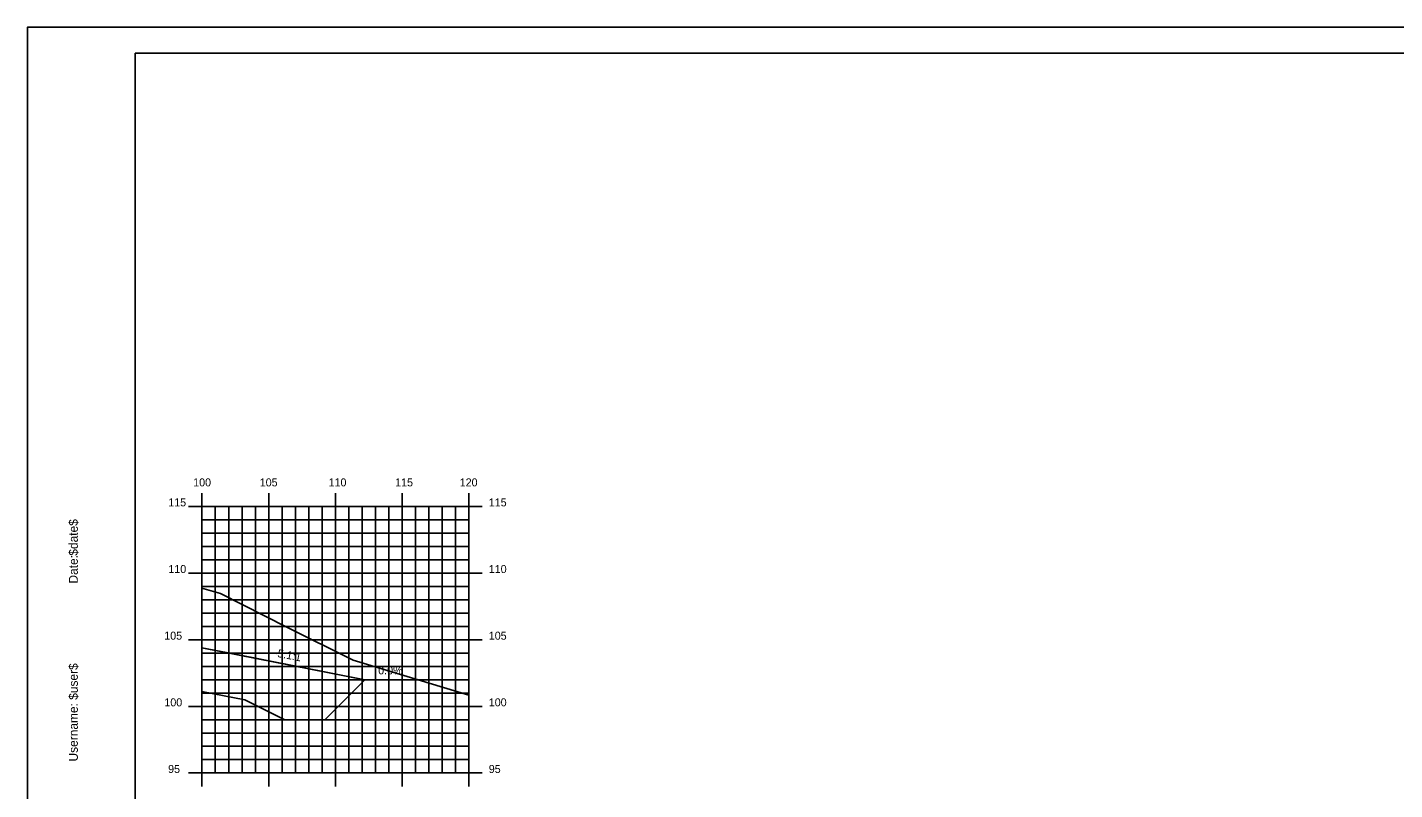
# Model space of a CAD drawing. Extents: x 850598 to 870284, y 366541 to 366651.
# Drawn here: x 856807 to 856909.5, y 366594 to 366651.2 of the extents above; entities that cross this region are included whole.
import ezdxf

# ---------------------------------------------------------------- set-up
doc = ezdxf.new("R2010")
doc.units = 0
for name, color, linetype in [('ANNOTATION', 7, 'Continuous'), ('BORDER', 7, 'Continuous'), ('D_Drainage_RipRap', 7, 'Continuous'), ('D_Roadway_Centerline', 7, 'Continuous'), ('D_Roadway_SlopeLines', 7, 'Continuous'), ('H_V ANNOTATION', 7, 'Continuous'), ('MAJOR', 7, 'Continuous'), ('MINOR', 7, 'Continuous'), ('PLOT BOUNDARY', 7, 'Continuous'), ('S_Roadway_Centerline', 7, 'Continuous')]:
    doc.layers.add(name, color=color, linetype=linetype)

msp = doc.modelspace()

# ---------------------------------------------------------------- linework, layer by layer
at = {"layer": 'BORDER'}
for p, q in [((856975.08, 366649.23), (856815.08, 366649.23)), ((856815.08, 366649.23), (856815.08, 366544.23))]:
    msp.add_line(p, q, dxfattribs=at)
at = {"layer": 'D_Drainage_RipRap'}
msp.add_lwpolyline([(856820.08, 366601.34), (856820.08, 366604.62), (856822.43, 366604.16), (856832.29, 366602.23), (856829.29, 366599.23), (856826.29, 366599.23), (856823.29, 366600.71)], close=True, dxfattribs=at)
at = {"layer": 'D_Roadway_Centerline'}
msp.add_lwpolyline([(856820.08, 366604.62), (856822.43, 366604.16), (856832.29, 366602.23), (856836.29, 366602.23)], dxfattribs=at)
at = {"layer": 'D_Roadway_SlopeLines'}
msp.add_lwpolyline([(856820.08, 366604.62), (856832.29, 366602.23)], dxfattribs=at)
at = {"layer": 'MAJOR'}
for p, q in [((856820.08, 366616.23), (856820.08, 366615.23)), ((856820.08, 366616.23), (856820.08, 366615.23)), ((856825.08, 366616.23), (856825.08, 366615.23)), ((856825.08, 366616.23), (856825.08, 366615.23)), ((856830.08, 366616.23), (856830.08, 366615.23)), ((856830.08, 366616.23), (856830.08, 366615.23)), ((856835.08, 366616.23), (856835.08, 366615.23)), ((856835.08, 366616.23), (856835.08, 366615.23)), ((856840.08, 366616.23), (856840.08, 366615.23)), ((856840.08, 366616.23), (856840.08, 366615.23)), ((856819.08, 366615.23), (856820.08, 366615.23)), ((856819.08, 366615.23), (856820.08, 366615.23)), ((856820.08, 366615.23), (856840.08, 366615.23)), ((856820.08, 366595.23), (856820.08, 366615.23)), ((856820.08, 366595.23), (856820.08, 366615.23)), ((856820.08, 366615.23), (856840.08, 366615.23)), ((856820.08, 366615.23), (856840.08, 366615.23)), ((856820.08, 366595.23), (856820.08, 366615.23)), ((856820.08, 366595.23), (856820.08, 366615.23)), ((856820.08, 366615.23), (856840.08, 366615.23)), ((856825.08, 366595.23), (856825.08, 366615.23)), ((856825.08, 366595.23), (856825.08, 366615.23)), ((856830.08, 366595.23), (856830.08, 366615.23)), ((856830.08, 366595.23), (856830.08, 366615.23)), ((856835.08, 366595.23), (856835.08, 366615.23)), ((856835.08, 366595.23), (856835.08, 366615.23)), ((856841.08, 366615.23), (856839.08, 366615.23)), ((856841.08, 366615.23), (856839.08, 366615.23)), ((856840.08, 366595.23), (856840.08, 366615.23)), ((856840.08, 366595.23), (856840.08, 366615.23)), ((856840.08, 366595.23), (856840.08, 366615.23)), ((856840.08, 366595.23), (856840.08, 366615.23)), ((856819.08, 366610.23), (856820.08, 366610.23)), ((856819.08, 366610.23), (856820.08, 366610.23)), ((856820.08, 366610.23), (856840.08, 366610.23)), ((856820.08, 366610.23), (856840.08, 366610.23)), ((856841.08, 366610.23), (856839.08, 366610.23)), ((856841.08, 366610.23), (856839.08, 366610.23)), ((856819.08, 366605.23), (856820.08, 366605.23)), ((856819.08, 366605.23), (856820.08, 366605.23)), ((856820.08, 366605.23), (856840.08, 366605.23)), ((856820.08, 366605.23), (856840.08, 366605.23)), ((856841.08, 366605.23), (856839.08, 366605.23)), ((856841.08, 366605.23), (856839.08, 366605.23)), ((856819.08, 366600.23), (856820.08, 366600.23)), ((856819.08, 366600.23), (856820.08, 366600.23)), ((856820.08, 366600.23), (856840.08, 366600.23)), ((856820.08, 366600.23), (856840.08, 366600.23)), ((856841.08, 366600.23), (856839.08, 366600.23)), ((856841.08, 366600.23), (856839.08, 366600.23)), ((856819.08, 366595.23), (856820.08, 366595.23)), ((856819.08, 366595.23), (856820.08, 366595.23)), ((856820.08, 366595.23), (856840.08, 366595.23)), ((856820.08, 366595.23), (856840.08, 366595.23)), ((856820.08, 366594.22), (856820.08, 366595.23)), ((856820.08, 366595.23), (856840.08, 366595.23)), ((856820.08, 366595.23), (856840.08, 366595.23)), ((856820.08, 366594.22), (856820.08, 366595.23)), ((856825.08, 366594.22), (856825.08, 366595.23)), ((856825.08, 366594.22), (856825.08, 366595.23)), ((856830.08, 366594.22), (856830.08, 366595.23)), ((856830.08, 366594.22), (856830.08, 366595.23)), ((856835.08, 366594.22), (856835.08, 366595.23)), ((856835.08, 366594.22), (856835.08, 366595.23)), ((856841.08, 366595.23), (856839.08, 366595.23)), ((856841.08, 366595.23), (856839.08, 366595.23)), ((856840.08, 366594.22), (856840.08, 366595.23)), ((856840.08, 366594.22), (856840.08, 366595.23))]:
    msp.add_line(p, q, dxfattribs=at)
at = {"layer": 'MINOR'}
for p, q in [((856821.08, 366595.23), (856821.08, 366615.23)), ((856821.08, 366595.23), (856821.08, 366615.23)), ((856822.08, 366595.23), (856822.08, 366615.23)), ((856822.08, 366595.23), (856822.08, 366615.23)), ((856823.08, 366595.23), (856823.08, 366615.23)), ((856823.08, 366595.23), (856823.08, 366615.23)), ((856824.08, 366595.23), (856824.08, 366615.23)), ((856824.08, 366595.23), (856824.08, 366615.23)), ((856826.08, 366595.23), (856826.08, 366615.23)), ((856826.08, 366595.23), (856826.08, 366615.23)), ((856827.08, 366595.23), (856827.08, 366615.23)), ((856827.08, 366595.23), (856827.08, 366615.23)), ((856828.08, 366595.23), (856828.08, 366615.23)), ((856828.08, 366595.23), (856828.08, 366615.23)), ((856829.08, 366595.23), (856829.08, 366615.23)), ((856829.08, 366595.23), (856829.08, 366615.23)), ((856831.08, 366595.23), (856831.08, 366615.23)), ((856831.08, 366595.23), (856831.08, 366615.23)), ((856832.08, 366595.23), (856832.08, 366615.23)), ((856832.08, 366595.23), (856832.08, 366615.23)), ((856833.08, 366595.23), (856833.08, 366615.23)), ((856833.08, 366595.23), (856833.08, 366615.23)), ((856834.08, 366595.23), (856834.08, 366615.23)), ((856834.08, 366595.23), (856834.08, 366615.23)), ((856836.08, 366595.23), (856836.08, 366615.23)), ((856836.08, 366595.23), (856836.08, 366615.23)), ((856837.08, 366595.23), (856837.08, 366615.23)), ((856837.08, 366595.23), (856837.08, 366615.23)), ((856838.08, 366595.23), (856838.08, 366615.23)), ((856838.08, 366595.23), (856838.08, 366615.23)), ((856839.08, 366595.23), (856839.08, 366615.23)), ((856839.08, 366595.23), (856839.08, 366615.23)), ((856820.08, 366614.23), (856840.08, 366614.23)), ((856820.08, 366614.23), (856821.08, 366614.23)), ((856820.08, 366614.23), (856840.08, 366614.23)), ((856820.08, 366614.23), (856821.08, 366614.23)), ((856820.08, 366613.23), (856840.08, 366613.23)), ((856820.08, 366613.23), (856821.08, 366613.23)), ((856820.08, 366613.23), (856840.08, 366613.23)), ((856820.08, 366613.23), (856821.08, 366613.23)), ((856840.08, 366614.23), (856839.08, 366614.23)), ((856840.08, 366614.23), (856839.08, 366614.23)), ((856840.08, 366613.23), (856839.08, 366613.23)), ((856840.08, 366613.23), (856839.08, 366613.23)), ((856820.08, 366612.23), (856840.08, 366612.23)), ((856820.08, 366612.23), (856821.08, 366612.23)), ((856820.08, 366612.23), (856840.08, 366612.23)), ((856820.08, 366612.23), (856821.08, 366612.23)), ((856840.08, 366612.23), (856839.08, 366612.23)), ((856840.08, 366612.23), (856839.08, 366612.23)), ((856820.08, 366611.23), (856840.08, 366611.23)), ((856820.08, 366611.23), (856821.08, 366611.23)), ((856820.08, 366611.23), (856840.08, 366611.23)), ((856820.08, 366611.23), (856821.08, 366611.23)), ((856840.08, 366611.23), (856839.08, 366611.23)), ((856840.08, 366611.23), (856839.08, 366611.23)), ((856820.08, 366609.23), (856840.08, 366609.23)), ((856820.08, 366609.23), (856821.08, 366609.23)), ((856820.08, 366609.23), (856840.08, 366609.23)), ((856820.08, 366609.23), (856821.08, 366609.23)), ((856840.08, 366609.23), (856839.08, 366609.23)), ((856840.08, 366609.23), (856839.08, 366609.23)), ((856820.08, 366608.23), (856840.08, 366608.23)), ((856820.08, 366608.23), (856821.08, 366608.23)), ((856820.08, 366608.23), (856840.08, 366608.23)), ((856820.08, 366608.23), (856821.08, 366608.23)), ((856840.08, 366608.23), (856839.08, 366608.23)), ((856840.08, 366608.23), (856839.08, 366608.23)), ((856820.08, 366607.23), (856840.08, 366607.23)), ((856820.08, 366607.23), (856821.08, 366607.23)), ((856820.08, 366607.23), (856840.08, 366607.23)), ((856820.08, 366607.23), (856821.08, 366607.23)), ((856840.08, 366607.23), (856839.08, 366607.23)), ((856840.08, 366607.23), (856839.08, 366607.23)), ((856820.08, 366606.23), (856840.08, 366606.23)), ((856820.08, 366606.23), (856821.08, 366606.23)), ((856820.08, 366606.23), (856840.08, 366606.23)), ((856820.08, 366606.23), (856821.08, 366606.23)), ((856840.08, 366606.23), (856839.08, 366606.23)), ((856840.08, 366606.23), (856839.08, 366606.23)), ((856820.08, 366604.23), (856840.08, 366604.23)), ((856820.08, 366604.23), (856821.08, 366604.23)), ((856820.08, 366604.23), (856840.08, 366604.23)), ((856820.08, 366604.23), (856821.08, 366604.23)), ((856840.08, 366604.23), (856839.08, 366604.23)), ((856840.08, 366604.23), (856839.08, 366604.23)), ((856820.08, 366603.23), (856840.08, 366603.23)), ((856820.08, 366603.23), (856821.08, 366603.23)), ((856820.08, 366603.23), (856840.08, 366603.23)), ((856820.08, 366603.23), (856821.08, 366603.23)), ((856840.08, 366603.23), (856839.08, 366603.23)), ((856840.08, 366603.23), (856839.08, 366603.23)), ((856820.08, 366602.23), (856840.08, 366602.23)), ((856820.08, 366602.23), (856821.08, 366602.23)), ((856820.08, 366602.23), (856840.08, 366602.23)), ((856820.08, 366602.23), (856821.08, 366602.23)), ((856840.08, 366602.23), (856839.08, 366602.23)), ((856840.08, 366602.23), (856839.08, 366602.23)), ((856820.08, 366601.23), (856840.08, 366601.23)), ((856820.08, 366601.23), (856821.08, 366601.23)), ((856820.08, 366601.23), (856840.08, 366601.23)), ((856820.08, 366601.23), (856821.08, 366601.23)), ((856840.08, 366601.23), (856839.08, 366601.23)), ((856840.08, 366601.23), (856839.08, 366601.23)), ((856820.08, 366599.23), (856840.08, 366599.23)), ((856820.08, 366599.23), (856821.08, 366599.23)), ((856820.08, 366599.23), (856840.08, 366599.23)), ((856820.08, 366599.23), (856821.08, 366599.23)), ((856840.08, 366599.23), (856839.08, 366599.23)), ((856840.08, 366599.23), (856839.08, 366599.23)), ((856820.08, 366598.23), (856840.08, 366598.23)), ((856820.08, 366598.23), (856821.08, 366598.23)), ((856820.08, 366598.23), (856840.08, 366598.23)), ((856820.08, 366598.23), (856821.08, 366598.23)), ((856840.08, 366598.23), (856839.08, 366598.23)), ((856840.08, 366598.23), (856839.08, 366598.23)), ((856820.08, 366597.23), (856840.08, 366597.23)), ((856820.08, 366597.23), (856821.08, 366597.23)), ((856820.08, 366597.23), (856840.08, 366597.23)), ((856820.08, 366597.23), (856821.08, 366597.23)), ((856840.08, 366597.23), (856839.08, 366597.23)), ((856840.08, 366597.23), (856839.08, 366597.23)), ((856820.08, 366596.23), (856840.08, 366596.23)), ((856820.08, 366596.23), (856821.08, 366596.23)), ((856820.08, 366596.23), (856840.08, 366596.23)), ((856820.08, 366596.23), (856821.08, 366596.23)), ((856840.08, 366596.23), (856839.08, 366596.23)), ((856840.08, 366596.23), (856839.08, 366596.23))]:
    msp.add_line(p, q, dxfattribs=at)
at = {"layer": 'PLOT BOUNDARY'}
msp.add_lwpolyline([(856806.99, 366541.17), (856976.99, 366541.17), (856976.99, 366651.17), (856806.99, 366651.17)], close=True, dxfattribs=at)
at = {"layer": 'S_Roadway_Centerline'}
msp.add_lwpolyline([(856820.08, 366609.1), (856821.46, 366608.69), (856826.45, 366606.16), (856831.41, 366603.7), (856840.08, 366601.08)], dxfattribs=at)

# ---------------------------------------------------------------- texts
at = {"layer": 'ANNOTATION'}
msp.add_text('-5.1:1', height=0.6, rotation=348.8991, dxfattribs=at).set_placement((856825.44, 366603.99))
msp.add_text('0.0%', height=0.6, dxfattribs=at).set_placement((856833.29, 366602.63))
at = {"layer": 'BORDER'}
for s, p in [('$date$', (856810.77, 366611.53)), ('Date:', (856810.77, 366609.44)), ('$user$', (856810.77, 366600.72)), ('Username:', (856810.77, 366596.09))]:
    msp.add_text(s, height=0.67, rotation=90, dxfattribs=at).set_placement(p)
at = {"layer": 'H_V ANNOTATION'}
for s, p in [('100', (856819.42, 366616.73)), ('105', (856824.41, 366616.73)), ('110', (856829.57, 366616.73)), ('115', (856834.56, 366616.73)), ('120', (856839.4, 366616.73)), ('115', (856817.55, 366615.23)), ('115', (856841.58, 366615.23)), ('110', (856817.56, 366610.23)), ('110', (856841.58, 366610.23)), ('105', (856817.25, 366605.23)), ('105', (856841.58, 366605.23)), ('100', (856817.26, 366600.23)), ('100', (856841.58, 366600.23)), ('95', (856817.54, 366595.23)), ('95', (856841.58, 366595.23))]:
    msp.add_text(s, height=0.6, dxfattribs=at).set_placement(p)

doc.saveas('drawing.dxf')
